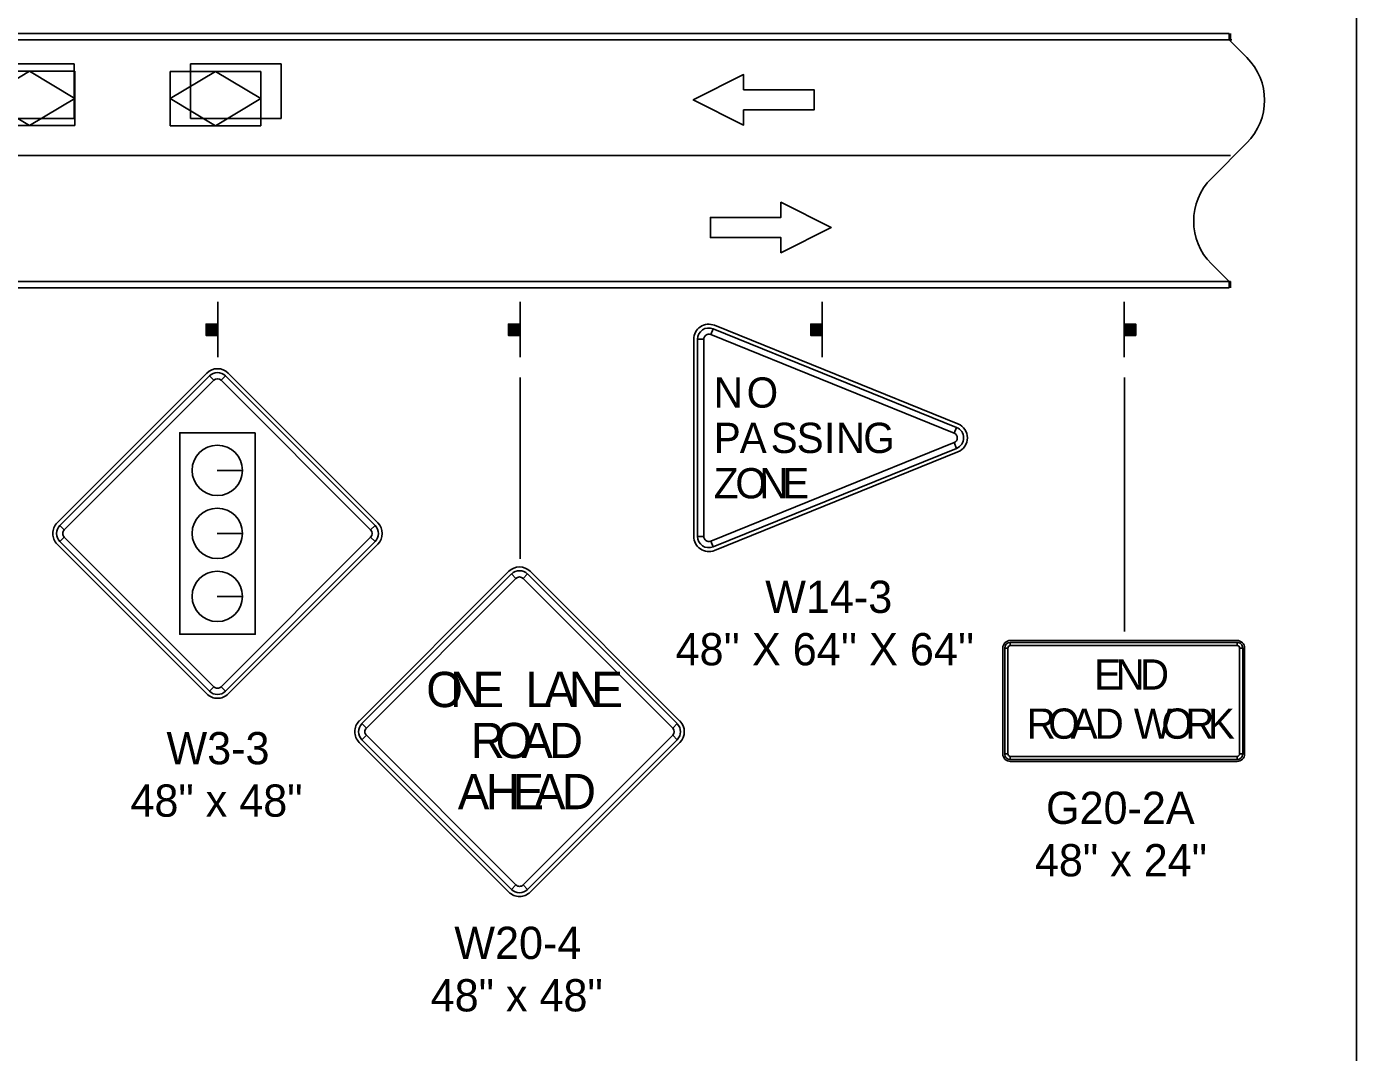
# Model space of a CAD drawing. Extents: x -2134934 to -2127057, y -2139046 to -2137036.
# Drawn here: x -2127757 to -2127097, y -2138047 to -2137539 of the extents above; entities that cross this region are included whole.
import ezdxf

# ---------------------------------------------------------------- set-up
doc = ezdxf.new("R2010")
doc.units = 0
for name, color, linetype in [('Barrier', 7, 'Continuous'), ('BridgeSuperStructureExisting', 7, 'Continuous'), ('Default', 7, 'Continuous'), ('DsnShtPlotIdentification', 7, 'Continuous'), ('dsnTextFinalPlan', 7, 'Continuous')]:
    doc.layers.add(name, color=color, linetype=linetype)

msp = doc.modelspace()

# ---------------------------------------------------------------- linework, layer by layer
at = {"layer": 'Barrier'}
for p, q in [((-2127417.35, -2137691.45), (-2127416.18, -2137688.56)), ((-2127294.65, -2137735.69), (-2127415.48, -2137686.82)), ((-2127425.79, -2137693.77), (-2127425.79, -2137791.52)), ((-2127423.92, -2137693.77), (-2127420.79, -2137693.77)), ((-2127667.38, -2137710.55), (-2127741.62, -2137784.8)), ((-2127666.05, -2137711.88), (-2127663.84, -2137714.08)), ((-2127660.31, -2137714.08), (-2127658.1, -2137711.88)), ((-2127582.52, -2137784.8), (-2127656.77, -2137710.55)), ((-2127295.36, -2137737.43), (-2127296.53, -2137740.33)), ((-2127296.53, -2137744.96), (-2127295.36, -2137747.86)), ((-2127415.48, -2137798.48), (-2127294.65, -2137749.6)), ((-2127649.67, -2137758.77), (-2127662.17, -2137758.77)), ((-2127662.17, -2137758.77), (-2127649.67, -2137758.77)), ((-2127738.09, -2137788.33), (-2127740.3, -2137786.12)), ((-2127649.67, -2137790.02), (-2127662.17, -2137790.02)), ((-2127662.17, -2137790.02), (-2127649.67, -2137790.02)), ((-2127583.85, -2137786.12), (-2127586.06, -2137788.33)), ((-2127420.79, -2137791.52), (-2127423.92, -2137791.52)), ((-2127741.62, -2137795.4), (-2127667.38, -2137869.65)), ((-2127740.3, -2137794.08), (-2127738.09, -2137791.87)), ((-2127656.77, -2137869.65), (-2127582.52, -2137795.4)), ((-2127586.06, -2137791.87), (-2127583.85, -2137794.08)), ((-2127416.18, -2137796.74), (-2127417.35, -2137793.84)), ((-2127517.49, -2137808.84), (-2127591.74, -2137883.09)), ((-2127516.17, -2137810.17), (-2127513.96, -2137812.38)), ((-2127510.42, -2137812.38), (-2127508.21, -2137810.17)), ((-2127432.64, -2137883.09), (-2127506.89, -2137808.84)), ((-2127649.67, -2137821.27), (-2127662.17, -2137821.27)), ((-2127662.17, -2137821.27), (-2127649.67, -2137821.27)), ((-2127156.17, -2137843.14), (-2127268.67, -2137843.14)), ((-2127268.67, -2137845.64), (-2127268.67, -2137844.08)), ((-2127156.17, -2137844.08), (-2127156.17, -2137845.64)), ((-2127272.42, -2137846.89), (-2127272.42, -2137899.39)), ((-2127271.48, -2137846.89), (-2127269.92, -2137846.89)), ((-2127154.92, -2137846.89), (-2127153.35, -2137846.89)), ((-2127152.42, -2137899.39), (-2127152.42, -2137846.89)), ((-2127663.84, -2137866.11), (-2127666.05, -2137868.32)), ((-2127658.1, -2137868.32), (-2127660.31, -2137866.11)), ((-2127588.2, -2137886.62), (-2127590.41, -2137884.41)), ((-2127590.41, -2137892.37), (-2127588.2, -2137890.16)), ((-2127433.97, -2137884.41), (-2127436.17, -2137886.62)), ((-2127436.17, -2137890.16), (-2127433.97, -2137892.37)), ((-2127591.74, -2137893.69), (-2127517.49, -2137967.94)), ((-2127506.89, -2137967.94), (-2127432.64, -2137893.69)), ((-2127269.92, -2137899.39), (-2127271.48, -2137899.39)), ((-2127268.67, -2137902.2), (-2127268.67, -2137900.64)), ((-2127268.67, -2137903.14), (-2127156.17, -2137903.14)), ((-2127156.17, -2137900.64), (-2127156.17, -2137902.2)), ((-2127153.35, -2137899.39), (-2127154.92, -2137899.39)), ((-2127513.96, -2137964.41), (-2127516.17, -2137966.61)), ((-2127508.21, -2137966.61), (-2127510.42, -2137964.41))]:
    msp.add_line(p, q, dxfattribs=at)
for points in [[(-2127295.36, -2137737.43), (-2127416.18, -2137688.56), (-2127417.35, -2137691.45), (-2127296.53, -2137740.33), (-2127295.36, -2137737.43)], [(-2127423.92, -2137693.77), (-2127423.92, -2137791.52), (-2127420.79, -2137791.52), (-2127420.79, -2137693.77), (-2127423.92, -2137693.77)], [(-2127666.05, -2137711.88), (-2127740.3, -2137786.12), (-2127738.09, -2137788.33), (-2127663.84, -2137714.08), (-2127666.05, -2137711.88)], [(-2127583.85, -2137786.12), (-2127658.1, -2137711.88), (-2127660.31, -2137714.08), (-2127586.06, -2137788.33), (-2127583.85, -2137786.12)], [(-2127643.34, -2137740.15), (-2127680.81, -2137740.15), (-2127680.81, -2137840.04), (-2127643.34, -2137840.04), (-2127643.34, -2137740.15)], [(-2127416.18, -2137796.74), (-2127295.36, -2137747.86), (-2127296.53, -2137744.96), (-2127417.35, -2137793.84), (-2127416.18, -2137796.74)], [(-2127740.3, -2137794.08), (-2127666.05, -2137868.32), (-2127663.84, -2137866.11), (-2127738.09, -2137791.87), (-2127740.3, -2137794.08)], [(-2127658.1, -2137868.32), (-2127583.85, -2137794.08), (-2127586.06, -2137791.87), (-2127660.31, -2137866.11), (-2127658.1, -2137868.32)], [(-2127516.17, -2137810.17), (-2127590.41, -2137884.41), (-2127588.2, -2137886.62), (-2127513.96, -2137812.38), (-2127516.17, -2137810.17)], [(-2127433.97, -2137884.41), (-2127508.21, -2137810.17), (-2127510.42, -2137812.38), (-2127436.17, -2137886.62), (-2127433.97, -2137884.41)], [(-2127156.17, -2137844.08), (-2127268.67, -2137844.08), (-2127268.67, -2137845.64), (-2127156.17, -2137845.64), (-2127156.17, -2137844.08)], [(-2127271.48, -2137846.89), (-2127271.48, -2137899.39), (-2127269.92, -2137899.39), (-2127269.92, -2137846.89), (-2127271.48, -2137846.89)], [(-2127153.35, -2137899.39), (-2127153.35, -2137846.89), (-2127154.92, -2137846.89), (-2127154.92, -2137899.39), (-2127153.35, -2137899.39)], [(-2127590.41, -2137892.37), (-2127516.17, -2137966.61), (-2127513.96, -2137964.41), (-2127588.2, -2137890.16), (-2127590.41, -2137892.37)], [(-2127508.21, -2137966.61), (-2127433.97, -2137892.37), (-2127436.17, -2137890.16), (-2127510.42, -2137964.41), (-2127508.21, -2137966.61)], [(-2127268.67, -2137902.2), (-2127156.17, -2137902.2), (-2127156.17, -2137900.64), (-2127268.67, -2137900.64), (-2127268.67, -2137902.2)]]:
    msp.add_lwpolyline(points, close=True, dxfattribs=at)
for centre in [(-2127662.17, -2137758.77), (-2127662.17, -2137790.02), (-2127662.17, -2137821.27)]:
    msp.add_circle(centre, 12.5, dxfattribs=at)
for centre, radius, start, end in [((-2127418.29, -2137693.77), 7.5, 67.97571, 179.99985), ((-2127418.29, -2137693.77), 5.62, 67.97571, 179.99985), ((-2127418.29, -2137693.77), 2.5, 67.97571, 179.99985), ((-2127662.07, -2137715.85), 7.5, 44.99999, 134.99974), ((-2127662.07, -2137715.85), 5.62, 44.99999, 134.99974), ((-2127662.07, -2137715.85), 2.5, 44.99999, 134.99974), ((-2127297.47, -2137742.65), 5.62, 292.02456, 67.97541), ((-2127297.47, -2137742.65), 7.5, 292.02456, 67.97598), ((-2127297.47, -2137742.65), 2.5, 292.02456, 67.97541), ((-2127736.32, -2137790.1), 7.5, 134.99974, 224.99995), ((-2127587.83, -2137790.1), 7.5, 315.00016, 44.9998), ((-2127736.32, -2137790.1), 5.62, 134.99974, 224.99995), ((-2127736.32, -2137790.1), 2.5, 134.99974, 224.99995), ((-2127587.83, -2137790.1), 2.5, 315.00016, 44.9998), ((-2127587.83, -2137790.1), 5.62, 315.00016, 44.9998), ((-2127418.29, -2137791.52), 7.5, 179.99985, 292.02456), ((-2127418.29, -2137791.52), 5.62, 179.99985, 292.02456), ((-2127418.29, -2137791.52), 2.5, 179.99985, 292.02456), ((-2127512.19, -2137814.15), 7.5, 44.99999, 134.99974), ((-2127512.19, -2137814.15), 5.62, 44.99999, 134.99974), ((-2127512.19, -2137814.15), 2.5, 44.99999, 134.99974), ((-2127268.67, -2137846.89), 3.75, 90.00021, 179.99985), ((-2127268.67, -2137846.89), 2.81, 90.00021, 179.99985), ((-2127156.17, -2137846.89), 3.75, 0, 90.00021), ((-2127156.17, -2137846.89), 2.81, 0, 90.00021), ((-2127268.67, -2137846.89), 1.25, 90.00021, 179.99985), ((-2127156.17, -2137846.89), 1.25, 0, 90.00021), ((-2127662.07, -2137864.34), 7.5, 224.99995, 315.00016), ((-2127662.07, -2137864.34), 5.62, 224.99995, 315.00016), ((-2127662.07, -2137864.34), 2.5, 224.99995, 315.00016), ((-2127586.43, -2137888.39), 7.5, 134.99974, 224.99995), ((-2127437.94, -2137888.39), 7.5, 315.00016, 44.9998), ((-2127586.43, -2137888.39), 5.62, 134.99974, 224.99995), ((-2127586.43, -2137888.39), 2.5, 134.99974, 224.99995), ((-2127437.94, -2137888.39), 2.5, 315.00016, 44.9998), ((-2127437.94, -2137888.39), 5.62, 315.00016, 44.9998), ((-2127268.67, -2137899.39), 3.75, 179.99985, 270.00006), ((-2127268.67, -2137899.39), 2.81, 179.99985, 270.00006), ((-2127268.67, -2137899.39), 1.25, 179.99985, 270.00006), ((-2127156.17, -2137899.39), 3.75, 270.00006, 0.00027), ((-2127156.17, -2137899.39), 2.81, 270.00006, 0.00027), ((-2127156.17, -2137899.39), 1.25, 270.00006, 0.00027), ((-2127512.19, -2137962.64), 7.5, 224.99995, 315.00016), ((-2127512.19, -2137962.64), 5.62, 224.99995, 315.00016), ((-2127512.19, -2137962.64), 2.5, 224.99995, 315.00016)]:
    msp.add_arc(centre, radius, start, end, dxfattribs=at)
at = {"layer": 'BridgeSuperStructureExisting'}
for p, q in [((-2127160.12, -2137545.16), (-2128660.12, -2137545.16)), ((-2127160.12, -2137545.16), (-2127151.33, -2137553.95)), ((-2127151.33, -2137553.95), (-2127160.12, -2137545.16)), ((-2127778.12, -2137557.19), (-2127733.12, -2137557.19)), ((-2127733.12, -2137557.19), (-2127778.12, -2137557.19)), ((-2127733.12, -2137557.19), (-2127733.12, -2137584.19)), ((-2127733.12, -2137584.19), (-2127733.12, -2137557.19)), ((-2127675.45, -2137557.19), (-2127630.45, -2137557.19)), ((-2127675.45, -2137584.19), (-2127675.45, -2137557.19)), ((-2127630.45, -2137557.19), (-2127675.45, -2137557.19)), ((-2127675.45, -2137557.19), (-2127675.45, -2137584.19)), ((-2127630.45, -2137557.19), (-2127630.45, -2137584.19)), ((-2127630.45, -2137584.19), (-2127630.45, -2137557.19)), ((-2127777.79, -2137560.78), (-2127732.79, -2137560.78)), ((-2127732.79, -2137587.78), (-2127732.79, -2137560.78)), ((-2127685.6, -2137587.86), (-2127685.6, -2137560.86)), ((-2127685.6, -2137560.86), (-2127640.6, -2137560.86)), ((-2127640.6, -2137587.86), (-2127640.6, -2137560.86)), ((-2127733.12, -2137584.19), (-2127778.12, -2137584.19)), ((-2127778.12, -2137584.19), (-2127733.12, -2137584.19)), ((-2127630.45, -2137584.19), (-2127675.45, -2137584.19)), ((-2127675.45, -2137584.19), (-2127630.45, -2137584.19)), ((-2127777.79, -2137587.78), (-2127732.79, -2137587.78)), ((-2127685.6, -2137587.86), (-2127640.6, -2137587.86)), ((-2127168.91, -2137613.95), (-2127151.33, -2137596.37)), ((-2127151.33, -2137596.38), (-2127168.9, -2137613.95)), ((-2127160.12, -2137665.16), (-2127168.91, -2137656.37)), ((-2127168.9, -2137656.38), (-2127160.12, -2137665.16)), ((-2128470.12, -2137665.16), (-2127160.12, -2137665.16)), ((-2127661.96, -2137702.66), (-2127661.96, -2137675.16)), ((-2127511.96, -2137702.66), (-2127511.96, -2137675.16)), ((-2127361.96, -2137702.66), (-2127361.96, -2137675.16)), ((-2127212.15, -2137702.66), (-2127212.15, -2137675.16)), ((-2127667.28, -2137691.8), (-2127667.28, -2137686.21)), ((-2127666.96, -2137686.21), (-2127666.96, -2137691.8)), ((-2127666.74, -2137691.8), (-2127666.74, -2137686.21)), ((-2127666.42, -2137686.21), (-2127666.42, -2137691.8)), ((-2127666.19, -2137691.8), (-2127666.21, -2137686.21)), ((-2127665.78, -2137686.21), (-2127665.76, -2137691.8)), ((-2127665.56, -2137691.8), (-2127665.56, -2137686.21)), ((-2127665.13, -2137686.21), (-2127665.13, -2137691.8)), ((-2127664.75, -2137691.8), (-2127664.75, -2137686.21)), ((-2127664.43, -2137686.21), (-2127664.41, -2137691.8)), ((-2127664.21, -2137691.8), (-2127664.21, -2137686.21)), ((-2127663.94, -2137686.21), (-2127663.94, -2137691.8)), ((-2127663.61, -2137691.8), (-2127663.61, -2137686.21)), ((-2127663.4, -2137686.21), (-2127663.4, -2137691.8)), ((-2127663.18, -2137691.8), (-2127663.18, -2137686.21)), ((-2127662.91, -2137686.21), (-2127662.91, -2137691.8)), ((-2127662.65, -2137691.8), (-2127662.65, -2137686.21)), ((-2127662.37, -2137686.21), (-2127662.37, -2137691.8)), ((-2127517.28, -2137691.8), (-2127517.28, -2137686.21)), ((-2127516.96, -2137686.21), (-2127516.96, -2137691.8)), ((-2127516.74, -2137691.8), (-2127516.74, -2137686.21)), ((-2127516.42, -2137686.21), (-2127516.42, -2137691.8)), ((-2127516.19, -2137691.8), (-2127516.21, -2137686.21)), ((-2127515.78, -2137686.21), (-2127515.76, -2137691.8)), ((-2127515.56, -2137691.8), (-2127515.56, -2137686.21)), ((-2127515.13, -2137686.21), (-2127515.13, -2137691.8)), ((-2127514.75, -2137691.8), (-2127514.75, -2137686.21)), ((-2127514.43, -2137686.21), (-2127514.41, -2137691.8)), ((-2127514.21, -2137691.8), (-2127514.21, -2137686.21)), ((-2127513.94, -2137686.21), (-2127513.94, -2137691.8)), ((-2127513.61, -2137691.8), (-2127513.61, -2137686.21)), ((-2127513.4, -2137686.21), (-2127513.4, -2137691.8)), ((-2127513.18, -2137691.8), (-2127513.18, -2137686.21)), ((-2127512.91, -2137686.21), (-2127512.91, -2137691.8)), ((-2127512.65, -2137691.8), (-2127512.65, -2137686.21)), ((-2127512.37, -2137686.21), (-2127512.37, -2137691.8)), ((-2127367.28, -2137691.8), (-2127367.28, -2137686.21)), ((-2127366.96, -2137686.21), (-2127366.96, -2137691.8)), ((-2127366.74, -2137691.8), (-2127366.74, -2137686.21)), ((-2127366.42, -2137686.21), (-2127366.42, -2137691.8)), ((-2127366.19, -2137691.8), (-2127366.21, -2137686.21)), ((-2127365.78, -2137686.21), (-2127365.76, -2137691.8)), ((-2127365.56, -2137691.8), (-2127365.56, -2137686.21)), ((-2127365.13, -2137686.21), (-2127365.13, -2137691.8)), ((-2127364.75, -2137691.8), (-2127364.75, -2137686.21)), ((-2127364.43, -2137686.21), (-2127364.41, -2137691.8)), ((-2127364.21, -2137691.8), (-2127364.21, -2137686.21)), ((-2127363.94, -2137686.21), (-2127363.94, -2137691.8)), ((-2127363.61, -2137691.8), (-2127363.61, -2137686.21)), ((-2127363.4, -2137686.21), (-2127363.4, -2137691.8)), ((-2127363.18, -2137691.8), (-2127363.18, -2137686.21)), ((-2127362.91, -2137686.21), (-2127362.91, -2137691.8)), ((-2127362.65, -2137691.8), (-2127362.65, -2137686.21)), ((-2127362.37, -2137686.21), (-2127362.37, -2137691.8)), ((-2127211.73, -2137686.21), (-2127211.73, -2137691.8)), ((-2127211.45, -2137691.8), (-2127211.45, -2137686.21)), ((-2127211.19, -2137686.21), (-2127211.19, -2137691.8)), ((-2127210.93, -2137691.8), (-2127210.93, -2137686.21)), ((-2127210.7, -2137686.21), (-2127210.7, -2137691.8)), ((-2127210.5, -2137691.8), (-2127210.5, -2137686.21)), ((-2127210.16, -2137686.21), (-2127210.16, -2137691.8)), ((-2127209.9, -2137691.8), (-2127209.9, -2137686.21)), ((-2127209.67, -2137686.21), (-2127209.69, -2137691.8)), ((-2127209.35, -2137691.8), (-2127209.35, -2137686.21)), ((-2127208.98, -2137686.21), (-2127208.98, -2137691.8)), ((-2127208.55, -2137691.8), (-2127208.55, -2137686.21)), ((-2127208.32, -2137686.21), (-2127208.34, -2137691.8)), ((-2127207.91, -2137691.8), (-2127207.89, -2137686.21)), ((-2127207.68, -2137686.21), (-2127207.68, -2137691.8)), ((-2127207.36, -2137691.8), (-2127207.36, -2137686.21)), ((-2127207.14, -2137686.21), (-2127207.14, -2137691.8)), ((-2127206.82, -2137691.8), (-2127206.82, -2137686.21)), ((-2127511.96, -2137802.66), (-2127511.96, -2137712.66)), ((-2127211.96, -2137838.71), (-2127211.96, -2137712.66))]:
    msp.add_line(p, q, dxfattribs=at)
for points in [[(-2127366.01, -2137579.99), (-2127366.01, -2137569.99), (-2127401.01, -2137569.99), (-2127401.01, -2137562.49), (-2127426.01, -2137574.99), (-2127401.01, -2137587.49), (-2127401.01, -2137579.99)], [(-2127417.52, -2137633.32), (-2127417.52, -2137643.32), (-2127382.52, -2137643.32), (-2127382.52, -2137650.82), (-2127357.52, -2137638.32), (-2127382.52, -2137625.82), (-2127382.52, -2137633.32)], [(-2127662.05, -2137686.21), (-2127662.05, -2137691.84), (-2127667.68, -2137691.84), (-2127667.68, -2137686.21)], [(-2127512.05, -2137686.21), (-2127512.05, -2137691.84), (-2127517.68, -2137691.84), (-2127517.68, -2137686.21)], [(-2127362.05, -2137686.21), (-2127362.05, -2137691.84), (-2127367.68, -2137691.84), (-2127367.68, -2137686.21)], [(-2127212.05, -2137686.21), (-2127212.05, -2137691.84), (-2127206.43, -2137691.84), (-2127206.43, -2137686.21)]]:
    msp.add_lwpolyline(points, close=True, dxfattribs=at)
for points in [[(-2127401.01, -2137579.99), (-2127401.01, -2137587.49), (-2127426.01, -2137574.99), (-2127401.01, -2137562.49), (-2127401.01, -2137569.99), (-2127366.01, -2137569.99), (-2127366.01, -2137579.99), (-2127401.01, -2137579.99)], [(-2127382.52, -2137633.32), (-2127382.52, -2137625.82), (-2127357.52, -2137638.32), (-2127382.52, -2137650.82), (-2127382.52, -2137643.32), (-2127417.52, -2137643.32), (-2127417.52, -2137633.32), (-2127382.52, -2137633.32)]]:
    msp.add_lwpolyline(points, dxfattribs=at)
for centre, start, end in [((-2127172.55, -2137575.16), 315, 45), ((-2127172.55, -2137575.16), 315, 45), ((-2127147.69, -2137635.16), 135, 225), ((-2127147.69, -2137635.16), 135, 225)]:
    msp.add_arc(centre, 30, start, end, dxfattribs=at)
at = {"layer": 'Default'}
msp.add_lwpolyline([(-2130231.95, -2137035.95), (-2127096.96, -2137035.95), (-2127096.96, -2139045.94), (-2130231.95, -2139045.94)], close=True, dxfattribs=at)
at = {"layer": 'DsnShtPlotIdentification'}
for p, q in [((-2127160.12, -2137542.16), (-2128660.12, -2137542.16)), ((-2127160.12, -2137542.16), (-2128660.12, -2137542.16)), ((-2127160.12, -2137545.16), (-2128660.12, -2137545.16)), ((-2127805.12, -2137545.16), (-2127160.12, -2137545.16)), ((-2127160.12, -2137545.16), (-2127160.12, -2137542.16)), ((-2127159.5, -2137542.16), (-2127159.5, -2137545.16)), ((-2127159.45, -2137602.66), (-2127811.95, -2137602.66)), ((-2128660.12, -2137665.16), (-2127159.5, -2137665.16)), ((-2127160.12, -2137665.16), (-2127758.7, -2137665.16)), ((-2127160.12, -2137668.16), (-2127160.12, -2137665.16)), ((-2127159.5, -2137668.16), (-2127159.5, -2137665.16)), ((-2127759.9, -2137668.16), (-2127160.12, -2137668.16))]:
    msp.add_line(p, q, dxfattribs=at)
for points in [[(-2128471.26, -2137545.16), (-2127158.8, -2137545.16)], [(-2127160.12, -2137665.16), (-2128470.12, -2137665.16)], [(-2127160.12, -2137668.16), (-2128470.12, -2137668.16)]]:
    msp.add_lwpolyline(points, dxfattribs=at)
at = {"layer": 'dsnTextFinalPlan'}
for points in [[(-2127777.79, -2137574.28), (-2127755.29, -2137560.78), (-2127732.79, -2137574.28), (-2127755.29, -2137587.78)], [(-2127685.6, -2137574.36), (-2127663.1, -2137560.86), (-2127640.6, -2137574.36), (-2127663.1, -2137587.86)]]:
    msp.add_lwpolyline(points, close=True, dxfattribs=at)

# ---------------------------------------------------------------- texts
at = {"layer": 'Barrier'}
for s, height, p in [('N', 15, (-2127415.82, -2137727.65)), ('O', 15, (-2127399.48, -2137727.65)), ('P', 15, (-2127415.82, -2137750.15)), ('A', 15, (-2127402.93, -2137750.15)), ('S', 15, (-2127387.58, -2137750.15)), ('S', 15, (-2127374.69, -2137750.15)), ('I', 15, (-2127361.09, -2137750.15)), ('N', 15, (-2127355.23, -2137750.15)), ('G', 15, (-2127341.64, -2137750.15)), ('Z', 15, (-2127415.82, -2137772.65)), ('O', 15, (-2127405.09, -2137772.65)), ('N', 15, (-2127393.26, -2137772.65)), ('E', 15, (-2127381.89, -2137772.65)), ('W14-3', 16, (-2127390.28, -2137829.48)), ("48'' X 64'' X 64''", 16, (-2127434.77, -2137855.47)), ('E', 15, (-2127227.09, -2137867.51)), ('N', 15, (-2127216.47, -2137867.51)), ('D', 15, (-2127204.39, -2137867.51)), ('O', 17.5, (-2127558.47, -2137876.2)), ('N', 17.5, (-2127546.7, -2137876.2)), ('E', 17.5, (-2127535.47, -2137876.2)), ('L', 17.5, (-2127509.22, -2137876.2)), ('A', 17.5, (-2127500.02, -2137876.2)), ('N', 17.5, (-2127487.76, -2137876.2)), ('E', 17.5, (-2127476.53, -2137876.2)), ('R', 15, (-2127260.56, -2137891.89)), ('O', 15, (-2127249.87, -2137891.89)), ('A', 15, (-2127238.72, -2137891.89)), ('D', 15, (-2127226.86, -2137891.89)), ('W', 15, (-2127207.4, -2137891.89)), ('O', 15, (-2127193.67, -2137891.89)), ('R', 15, (-2127181.9, -2137891.89)), ('K', 15, (-2127170.61, -2137891.89)), ('O', 17.5, (-2127524.08, -2137901.52)), ('W3-3', 16, (-2127687.37, -2137904.56)), ('R', 17.5, (-2127536.37, -2137901.52)), ('A', 17.5, (-2127511.24, -2137901.52)), ('D', 17.5, (-2127497.58, -2137901.52)), ('A', 17.5, (-2127542.8, -2137926.83)), ('H', 17.5, (-2127528.94, -2137926.83)), ('E', 17.5, (-2127515.72, -2137926.83)), ('A', 17.5, (-2127505.01, -2137926.83)), ('D', 17.5, (-2127491.14, -2137926.83)), ('48" x 48"', 16, (-2127705.24, -2137930.56)), ('G20-2A', 16, (-2127250.95, -2137934.14)), ('48" x 24"', 16, (-2127256.48, -2137960.14)), ('W20-4', 16, (-2127544.55, -2138001.14)), ('48" x 48"', 16, (-2127556.26, -2138027.14))]:
    msp.add_text(s, height=height, dxfattribs=at).set_placement(p)

doc.saveas('drawing.dxf')
